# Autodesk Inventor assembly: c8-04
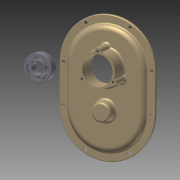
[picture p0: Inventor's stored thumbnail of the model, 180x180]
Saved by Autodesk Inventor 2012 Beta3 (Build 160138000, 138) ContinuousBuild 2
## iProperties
Created: 2010-12
Part Number: c8-04
Document SubType Name: Assembly
Designer: Beta-8540w
Author: Beta-8540w
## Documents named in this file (3)
- C:\Inventor 2012 Essentials\Assemblies\Chapter 8\c8-04.iam
- C:\Inventor 2012 Essentials\Parts\Chapter 8\c8-10.ipt
- C:\Inventor 2012 Essentials\Assemblies\Chapter 8\Design Accelerators\Bearing c8-01.iam
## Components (2 placed, 2 different names)
1. c8-10:1
2. Bearing:1 [sub-assembly]
